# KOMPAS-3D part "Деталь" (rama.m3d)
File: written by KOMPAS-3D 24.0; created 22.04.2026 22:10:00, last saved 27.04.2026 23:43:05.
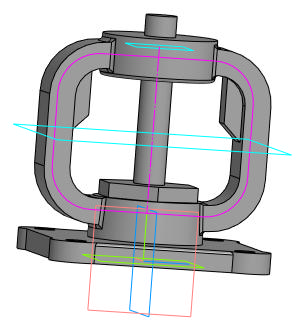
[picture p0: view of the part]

Document properties: Автор: mrdid; Полное имя файла: C:\Работа\ГОТОВЫЕ ИСХОДНИКИ\VSO2130M-F-S Клапан запорный сальниковый DN.ru Ду15-100 Ру40\исходные материалы\DN50\rama.m3d

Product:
- Part/product: Деталь
    Масса: 2.277187

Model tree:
1. Эскиз:2  (with: Ребро.Элемент выдавливания:14)
2. Элемент выдавливания:1
     Расстояние 1 = 10
3. Эскиз:3  (with: Грань.Элемент выдавливания:1, Ребро.Элемент выдавливания:1)
4. Элемент выдавливания:2
     Расстояние 2 = 10
5. Эскиз:4  (with: Грань.Элемент выдавливания:1)
6. Элемент выдавливания:3
     Угол 1 = -3
7. Эскиз:5  (with: Грань.Элемент выдавливания:3, Ребро.Элемент выдавливания:3)
8. Элемент выдавливания:4
9. Эскиз:23  (with: Грань.Элемент выдавливания:4, Ребро.Элемент выдавливания:4)
10. Элемент выдавливания:21  (labels: Деталь2; Грань.Твердое тело1)
     Расстояние 1 = 80.6397
11. Эскиз:7  (with: Грань.Элемент выдавливания:4, Ребро.Элемент выдавливания:3)
12. Элемент выдавливания:6  (with: Грань.Элемент выдавливания:3)
     Расстояние 2 = 7
13. Смещенная плоскость:4  (labels: Деталь2; Грань.Твердое тело1)
     Расстояние = 15
14. Эскиз:24  (with: Ребро.Элемент выдавливания:3)
15. Элемент выдавливания:22
     Расстояние 1 = 5; Расстояние 2 = 15
16. Эскиз:25  (with: Ребро.Элемент выдавливания:3)
17. Эскиз:26  (with: Ребро.Элемент выдавливания:3)
18. Элемент по траектории:1
     Длина траектории = 304.943
19. Скругление:8  (with: Ребро.Элемент по траектории:1)
     Радиус = 2
20. Скругление:9  (with: Ребро.Элемент по траектории:1)
     Радиус = 2
21. Смещенная плоскость:5  (with: Грань.Элемент выдавливания:1)
22. Эскиз:27  (with: Вершина.Элемент по траектории:1)
23. Элемент выдавливания:23  (with: Грань.Элемент выдавливания:22)
     Расстояние 1 = 34.3897; Смещение 1 = 5
24. Скругление:1  (with: Ребро.Элемент выдавливания:1)
     Радиус = 1.5
25. Скругление:10  (with: Ребро.Элемент выдавливания:22)
     Радиус = 1.5
26. Фаска:1  (with: Ребро.Элемент выдавливания:23)
     Угол = 45; Длина 1 = 10; Длина 2 = 10
27. Массив по концентрической сетке:1  (with: Элемент выдавливания:2, Эскиз:3)  (labels: Клапан запорный DN.ru Ду50 Ру40)  (4 pattern instances)
     Шаг 2 = 360

Expressions: DN/2; DN/4; H/4; DN/6
Referenced files in C:\Работа\ГОТОВЫЕ ИСХОДНИКИ\VSO2130M-F-S Клапан запорный сальниковый DN.ru Ду15-100 Ру40\исходные материалы\DN50\: VSO2130M-F-S Клапан запорный DN.ru Ду50 Ру40.a3d
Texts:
  DN+5
  Ось Y.Начало координат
